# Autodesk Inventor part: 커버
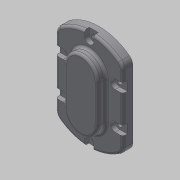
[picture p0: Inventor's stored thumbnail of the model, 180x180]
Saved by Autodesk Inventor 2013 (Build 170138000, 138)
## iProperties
Created: 2019-03
Part Number: 커버
Material: 알루미늄 6061
Document SubType Name: Modeling
Designer: mduedu
Density: 1 g/cm^3
Author: mduedu
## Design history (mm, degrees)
sketch "스케치1"
  geometry: L1 (44.721, -40)-(-44.721, -40); L2 (44.721, 40)-(-44.721, 40); A1 r 60 centre (0, 0) between (44.721, -40) and (44.721, 40); A2 r 60 centre (0, 0) between (-44.721, 40) and (-44.721, -40); 5 further points
  constraints: 6 point on circle, 4 end point, 2 centre point, 2 coincident, 2 horizontal alignment, 2 midpoint, 2 vertical alignment, 1 horizontal, 1 parallel
  dimensions: "d0" = 60 radius of A1; "d2" = 80 distance between parallel lines of L2 L1; "d3" = 120 distance of point (-60, 0) point (60, 0) (derived)
extrude "돌출1" new body sketch "스케치1" distance "d4" = 12; taper "d5" = 0 deg
sketch "스케치2"
  geometry: L1 (-20, -22)-(20, -22); L2 (20, -22)-(20, 22); L3 (20, 22)-(-20, 22); L4 (-20, 22)-(-20, -22); L5 (-20, -22)-(20, 22); L6 (20, -22)-(-20, 22); 3 further points
  constraints: 12 end point, 4 midpoint, 2 horizontal alignment, 2 parallel, 1 horizontal, 1 perpendicular, 4 other
  dimensions: "d6" = 40 distance between parallel lines of L2 L4; "d8" = 44 distance between parallel lines of L1 L3
extrude "돌출2" join sketch "스케치2" distance "d9" = 10; taper "d10" = 0 deg
fillet "모깎기1" dims "d11" = 10
fillet "모깎기2" dims "d12" = 3
sketch "스케치3"
  geometry: L1 (31, -22)-(31, 22); L2 (-31, 22)-(-31, -22); L3 (-31, -22)-(31, 22); L4 (31, -22)-(-31, 22); A1 r 31 centre (0, 22) between (31, 22) and (-31, 22); A2 r 31 centre (0, -22) between (-31, -22) and (31, -22); 7 further points
  constraints: 8 end point, 6 point on circle, 4 coincident, 3 tangent, 2 centre point, 2 midpoint, 1 parallel, 1 vertical, 1 vertical alignment
  dimensions: "d13" = 31 radius of A1; "d15" = 44 distance of A2.centre A1.centre
hole "구멍2" sketch "스케치3" at (-31, 22), (-31, -22), (31, -22), (31, 22), (0, 53), (0, -53) diameter "d28" = 5.5; stored, may be unused: countersink angle "d32" = 90 deg, drill point angle "d34" = 118 deg; dims "d29" = 6, "d30" = 4, "d31" = 2, "d33" = 8
sketch "스케치5"
  geometry: L1 (-40, 40)-(-40, -40) reference; L2 (40, -40)-(40, 40) reference; L3 (-5.5, 53)-(-5.5, 59.747); L4 (5.5, 53)-(5.5, 59.747); L5 (-31, 27.5)-(-40, 27.5); L6 (-31, 16.5)-(-40, 16.5); L7 (-31, -16.5)-(-40, -16.5); L8 (-31, -27.5)-(-40, -27.5); L9 (-5.5, -53)-(-5.5, -59.747); L10 (5.5, -53)-(5.5, -59.747); L11 (31, -27.5)-(40, -27.5); L12 (31, -16.5)-(40, -16.5); L13 (31, 16.5)-(40, 16.5); L14 (31, 27.5)-(40, 27.5); C1 r 2.75 at (0, 53) reference; C2 r 2.75 at (-31, 22) reference; C3 r 2.75 at (-31, -22) reference; C4 r 2.75 at (0, -53) reference; C5 r 2.75 at (31, -22) reference; C6 r 2.75 at (31, 22) reference; A1 r 60 centre (0, 0) between (36, 48) and (-36, 48) reference; A2 r 10 centre (-30, 40) between (-36, 48) and (-40, 40) reference; A3 r 10 centre (-30, -40) between (-40, -40) and (-36, -48) reference; A4 r 60 centre (0, 0) between (-36, -48) and (36, -48) reference; A5 r 10 centre (30, -40) between (36, -48) and (40, -40) reference; A6 r 10 centre (30, 40) between (40, 40) and (36, 48) reference; A7 r 5.5 centre (0, 53) between (-5.5, 53) and (5.5, 53); A8 r 5.5 centre (-31, 22) between (-31, 16.5) and (-31, 27.5); A9 r 5.5 centre (-31, -22) between (-31, -27.5) and (-31, -16.5); A10 r 5.5 centre (0, -53) between (5.5, -53) and (-5.5, -53); A11 r 5.5 centre (31, -22) between (31, -16.5) and (31, -27.5); A12 r 5.5 centre (31, 22) between (31, 27.5) and (31, 16.5); 1 further point
  constraints: 24 end point, 16 point on circle, 12 tangent, 8 parallel, 8 point on line, 6 centre point, 5 concentric, 4 horizontal, 1 coincident, 1 vertical
  dimensions: "d35" = 11 diameter of A7; "d36" = 11 diameter of A8; "d37" = 11 diameter of A9; "d38" = 11 diameter of A10; "d39" = 11 diameter of A11; "d40" = 11 diameter of A12
extrude "돌출4" cut sketch "스케치5" distance "d41" = 5.4; taper "d42" = 0 deg
sketch "스케치6"
  geometry: C1 r 12.5 at (0, 22); 1 further point
  constraints: 1 centre point, 1 vertical alignment
  dimensions: "d43" = 25 diameter of C1; "d45" = 22 distance of C1.centre point (0, 0)
extrude "돌출5" cut sketch "스케치6" distance "d47" = 15; taper "d48" = 0 deg
node "솔리드1"
mirror "대칭1"
